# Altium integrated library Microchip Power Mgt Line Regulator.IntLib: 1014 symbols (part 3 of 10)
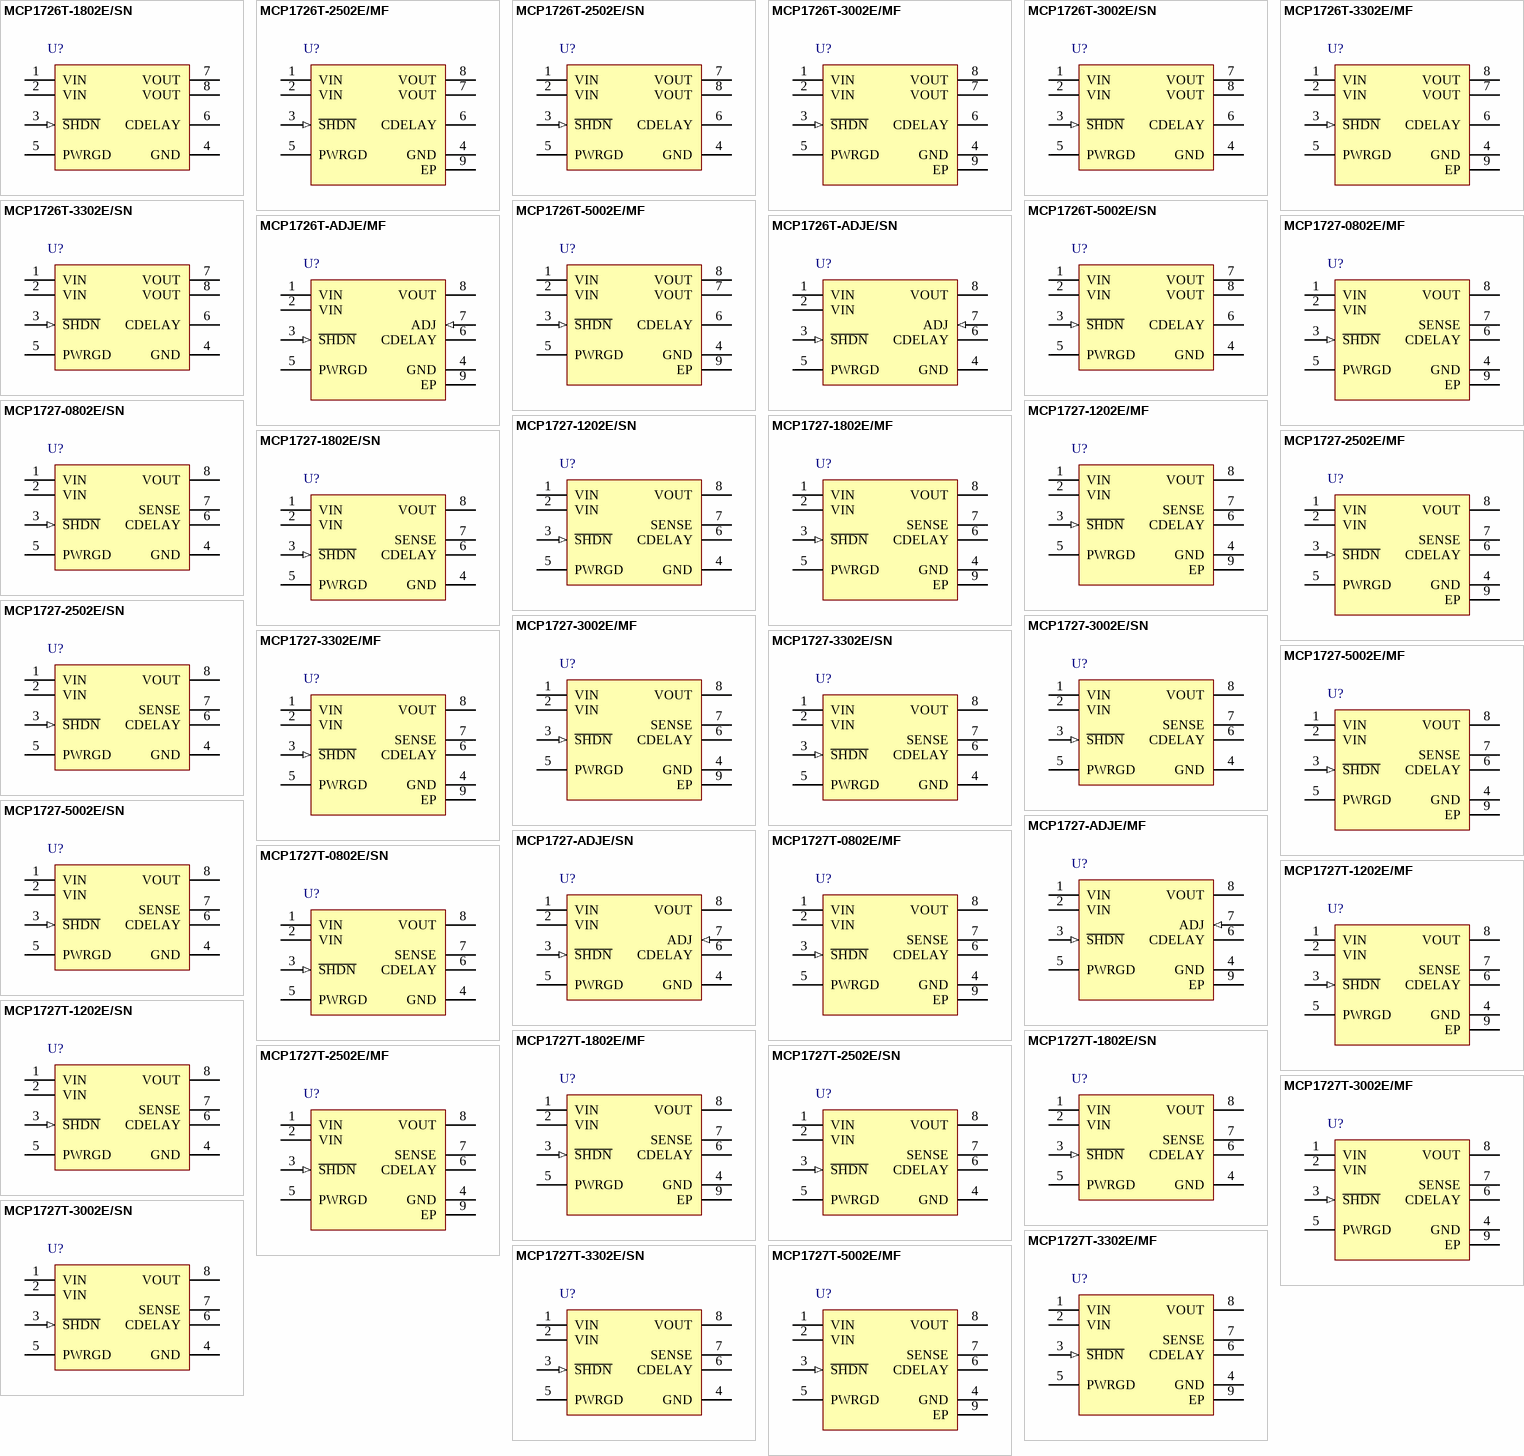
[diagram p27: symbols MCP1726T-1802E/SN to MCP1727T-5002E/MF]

## MCP1727-5002E/SN
designator U?
1.5A, Low Voltage, Low Quiescent Current LDO Regulator, 8-Pin SOIC 150mil, Extended Temperature
footprint SOIC-SN8_N (SOIC, 8-Leads, Body 4.9x3.8mm, Pitch 1.27mm, IPC Medium Density)
footprint SOIC-SN8_L (SOIC, 8-Leads, Body 4.9x3.8mm, Pitch 1.27mm, IPC High Density)
footprint SOIC-SN8_M (SOIC, 8-Leads, Body 4.9x3.8mm, Pitch 1.27mm, IPC Low Density)
pins: 1 VIN (power), 2 VIN (power), 3 ~{SHDN} (in), 4 GND (power), 5 PWRGD (power), 6 CDELAY, 7 SENSE, 8 VOUT (power)

## MCP1727-ADJE/MF
designator U?
1.5A, Low Voltage, Low Quiescent Current LDO Regulator, 8-Pin DFN, Extended Temperature
footprint DFN-MF8 (SON, 8-Leads, Body 3x3mm, Pitch 0.65mm, Microchip Recommended)
pins: 1 VIN (power), 2 VIN (power), 3 ~{SHDN} (in), 4 GND (power), 5 PWRGD (power), 6 CDELAY, 7 ADJ (in), 8 VOUT (power), 9 EP (power)

## MCP1727-ADJE/SN
designator U?
1.5A, Low Voltage, Low Quiescent Current LDO Regulator, 8-Pin SOIC 150mil, Extended Temperature
footprint SOIC-SN8_N (SOIC, 8-Leads, Body 4.9x3.8mm, Pitch 1.27mm, IPC Medium Density)
footprint SOIC-SN8_L (SOIC, 8-Leads, Body 4.9x3.8mm, Pitch 1.27mm, IPC High Density)
footprint SOIC-SN8_M (SOIC, 8-Leads, Body 4.9x3.8mm, Pitch 1.27mm, IPC Low Density)
pins: 1 VIN (power), 2 VIN (power), 3 ~{SHDN} (in), 4 GND (power), 5 PWRGD (power), 6 CDELAY, 7 ADJ (in), 8 VOUT (power)

## MCP1727T-0802E/MF
designator U?
1.5A, Low Voltage, Low Quiescent Current LDO Regulator, 8-Pin DFN, Extended Temperature, Tape and Reel
footprint DFN-MF8 (SON, 8-Leads, Body 3x3mm, Pitch 0.65mm, Microchip Recommended)
pins: 1 VIN (power), 2 VIN (power), 3 ~{SHDN} (in), 4 GND (power), 5 PWRGD (power), 6 CDELAY, 7 SENSE, 8 VOUT (power), 9 EP (power)

## MCP1727T-0802E/SN
designator U?
1.5A, Low Voltage, Low Quiescent Current LDO Regulator, 8-Pin SOIC 150mil, Extended Temperature, Tape and Reel
footprint SOIC-SN8_N (SOIC, 8-Leads, Body 4.9x3.8mm, Pitch 1.27mm, IPC Medium Density)
footprint SOIC-SN8_L (SOIC, 8-Leads, Body 4.9x3.8mm, Pitch 1.27mm, IPC High Density)
footprint SOIC-SN8_M (SOIC, 8-Leads, Body 4.9x3.8mm, Pitch 1.27mm, IPC Low Density)
pins: 1 VIN (power), 2 VIN (power), 3 ~{SHDN} (in), 4 GND (power), 5 PWRGD (power), 6 CDELAY, 7 SENSE, 8 VOUT (power)

## MCP1727T-1202E/MF
designator U?
1.5A, Low Voltage, Low Quiescent Current LDO Regulator, 8-Pin DFN, Extended Temperature, Tape and Reel
footprint DFN-MF8 (SON, 8-Leads, Body 3x3mm, Pitch 0.65mm, Microchip Recommended)
pins: 1 VIN (power), 2 VIN (power), 3 ~{SHDN} (in), 4 GND (power), 5 PWRGD (power), 6 CDELAY, 7 SENSE, 8 VOUT (power), 9 EP (power)

## MCP1727T-1202E/SN
designator U?
1.5A, Low Voltage, Low Quiescent Current LDO Regulator, 8-Pin SOIC 150mil, Extended Temperature, Tape and Reel
footprint SOIC-SN8_N (SOIC, 8-Leads, Body 4.9x3.8mm, Pitch 1.27mm, IPC Medium Density)
footprint SOIC-SN8_L (SOIC, 8-Leads, Body 4.9x3.8mm, Pitch 1.27mm, IPC High Density)
footprint SOIC-SN8_M (SOIC, 8-Leads, Body 4.9x3.8mm, Pitch 1.27mm, IPC Low Density)
pins: 1 VIN (power), 2 VIN (power), 3 ~{SHDN} (in), 4 GND (power), 5 PWRGD (power), 6 CDELAY, 7 SENSE, 8 VOUT (power)

## MCP1727T-1802E/MF
designator U?
1.5A, Low Voltage, Low Quiescent Current LDO Regulator, 8-Pin DFN, Extended Temperature, Tape and Reel
footprint DFN-MF8 (SON, 8-Leads, Body 3x3mm, Pitch 0.65mm, Microchip Recommended)
pins: 1 VIN (power), 2 VIN (power), 3 ~{SHDN} (in), 4 GND (power), 5 PWRGD (power), 6 CDELAY, 7 SENSE, 8 VOUT (power), 9 EP (power)

## MCP1727T-1802E/SN
designator U?
1.5A, Low Voltage, Low Quiescent Current LDO Regulator, 8-Pin SOIC 150mil, Extended Temperature, Tape and Reel
footprint SOIC-SN8_N (SOIC, 8-Leads, Body 4.9x3.8mm, Pitch 1.27mm, IPC Medium Density)
footprint SOIC-SN8_L (SOIC, 8-Leads, Body 4.9x3.8mm, Pitch 1.27mm, IPC High Density)
footprint SOIC-SN8_M (SOIC, 8-Leads, Body 4.9x3.8mm, Pitch 1.27mm, IPC Low Density)
pins: 1 VIN (power), 2 VIN (power), 3 ~{SHDN} (in), 4 GND (power), 5 PWRGD (power), 6 CDELAY, 7 SENSE, 8 VOUT (power)

## MCP1727T-2502E/MF
designator U?
1.5A, Low Voltage, Low Quiescent Current LDO Regulator, 8-Pin DFN, Extended Temperature, Tape and Reel
footprint DFN-MF8 (SON, 8-Leads, Body 3x3mm, Pitch 0.65mm, Microchip Recommended)
pins: 1 VIN (power), 2 VIN (power), 3 ~{SHDN} (in), 4 GND (power), 5 PWRGD (power), 6 CDELAY, 7 SENSE, 8 VOUT (power), 9 EP (power)

## MCP1727T-2502E/SN
designator U?
1.5A, Low Voltage, Low Quiescent Current LDO Regulator, 8-Pin SOIC 150mil, Extended Temperature, Tape and Reel
footprint SOIC-SN8_N (SOIC, 8-Leads, Body 4.9x3.8mm, Pitch 1.27mm, IPC Medium Density)
footprint SOIC-SN8_L (SOIC, 8-Leads, Body 4.9x3.8mm, Pitch 1.27mm, IPC High Density)
footprint SOIC-SN8_M (SOIC, 8-Leads, Body 4.9x3.8mm, Pitch 1.27mm, IPC Low Density)
pins: 1 VIN (power), 2 VIN (power), 3 ~{SHDN} (in), 4 GND (power), 5 PWRGD (power), 6 CDELAY, 7 SENSE, 8 VOUT (power)

## MCP1727T-3002E/MF
designator U?
1.5A, Low Voltage, Low Quiescent Current LDO Regulator, 8-Pin DFN, Extended Temperature, Tape and Reel
footprint DFN-MF8 (SON, 8-Leads, Body 3x3mm, Pitch 0.65mm, Microchip Recommended)
pins: 1 VIN (power), 2 VIN (power), 3 ~{SHDN} (in), 4 GND (power), 5 PWRGD (power), 6 CDELAY, 7 SENSE, 8 VOUT (power), 9 EP (power)

## MCP1727T-3002E/SN
designator U?
1.5A, Low Voltage, Low Quiescent Current LDO Regulator, 8-Pin SOIC 150mil, Extended Temperature, Tape and Reel
footprint SOIC-SN8_N (SOIC, 8-Leads, Body 4.9x3.8mm, Pitch 1.27mm, IPC Medium Density)
footprint SOIC-SN8_L (SOIC, 8-Leads, Body 4.9x3.8mm, Pitch 1.27mm, IPC High Density)
footprint SOIC-SN8_M (SOIC, 8-Leads, Body 4.9x3.8mm, Pitch 1.27mm, IPC Low Density)
pins: 1 VIN (power), 2 VIN (power), 3 ~{SHDN} (in), 4 GND (power), 5 PWRGD (power), 6 CDELAY, 7 SENSE, 8 VOUT (power)

## MCP1727T-3302E/MF
designator U?
1.5A, Low Voltage, Low Quiescent Current LDO Regulator, 8-Pin DFN, Extended Temperature, Tape and Reel
footprint DFN-MF8 (SON, 8-Leads, Body 3x3mm, Pitch 0.65mm, Microchip Recommended)
pins: 1 VIN (power), 2 VIN (power), 3 ~{SHDN} (in), 4 GND (power), 5 PWRGD (power), 6 CDELAY, 7 SENSE, 8 VOUT (power), 9 EP (power)

## MCP1727T-3302E/SN
designator U?
1.5A, Low Voltage, Low Quiescent Current LDO Regulator, 8-Pin SOIC 150mil, Extended Temperature, Tape and Reel
footprint SOIC-SN8_N (SOIC, 8-Leads, Body 4.9x3.8mm, Pitch 1.27mm, IPC Medium Density)
footprint SOIC-SN8_L (SOIC, 8-Leads, Body 4.9x3.8mm, Pitch 1.27mm, IPC High Density)
footprint SOIC-SN8_M (SOIC, 8-Leads, Body 4.9x3.8mm, Pitch 1.27mm, IPC Low Density)
pins: 1 VIN (power), 2 VIN (power), 3 ~{SHDN} (in), 4 GND (power), 5 PWRGD (power), 6 CDELAY, 7 SENSE, 8 VOUT (power)

## MCP1727T-5002E/MF
designator U?
1.5A, Low Voltage, Low Quiescent Current LDO Regulator, 8-Pin DFN, Extended Temperature, Tape and Reel
footprint DFN-MF8 (SON, 8-Leads, Body 3x3mm, Pitch 0.65mm, Microchip Recommended)
pins: 1 VIN (power), 2 VIN (power), 3 ~{SHDN} (in), 4 GND (power), 5 PWRGD (power), 6 CDELAY, 7 SENSE, 8 VOUT (power), 9 EP (power)

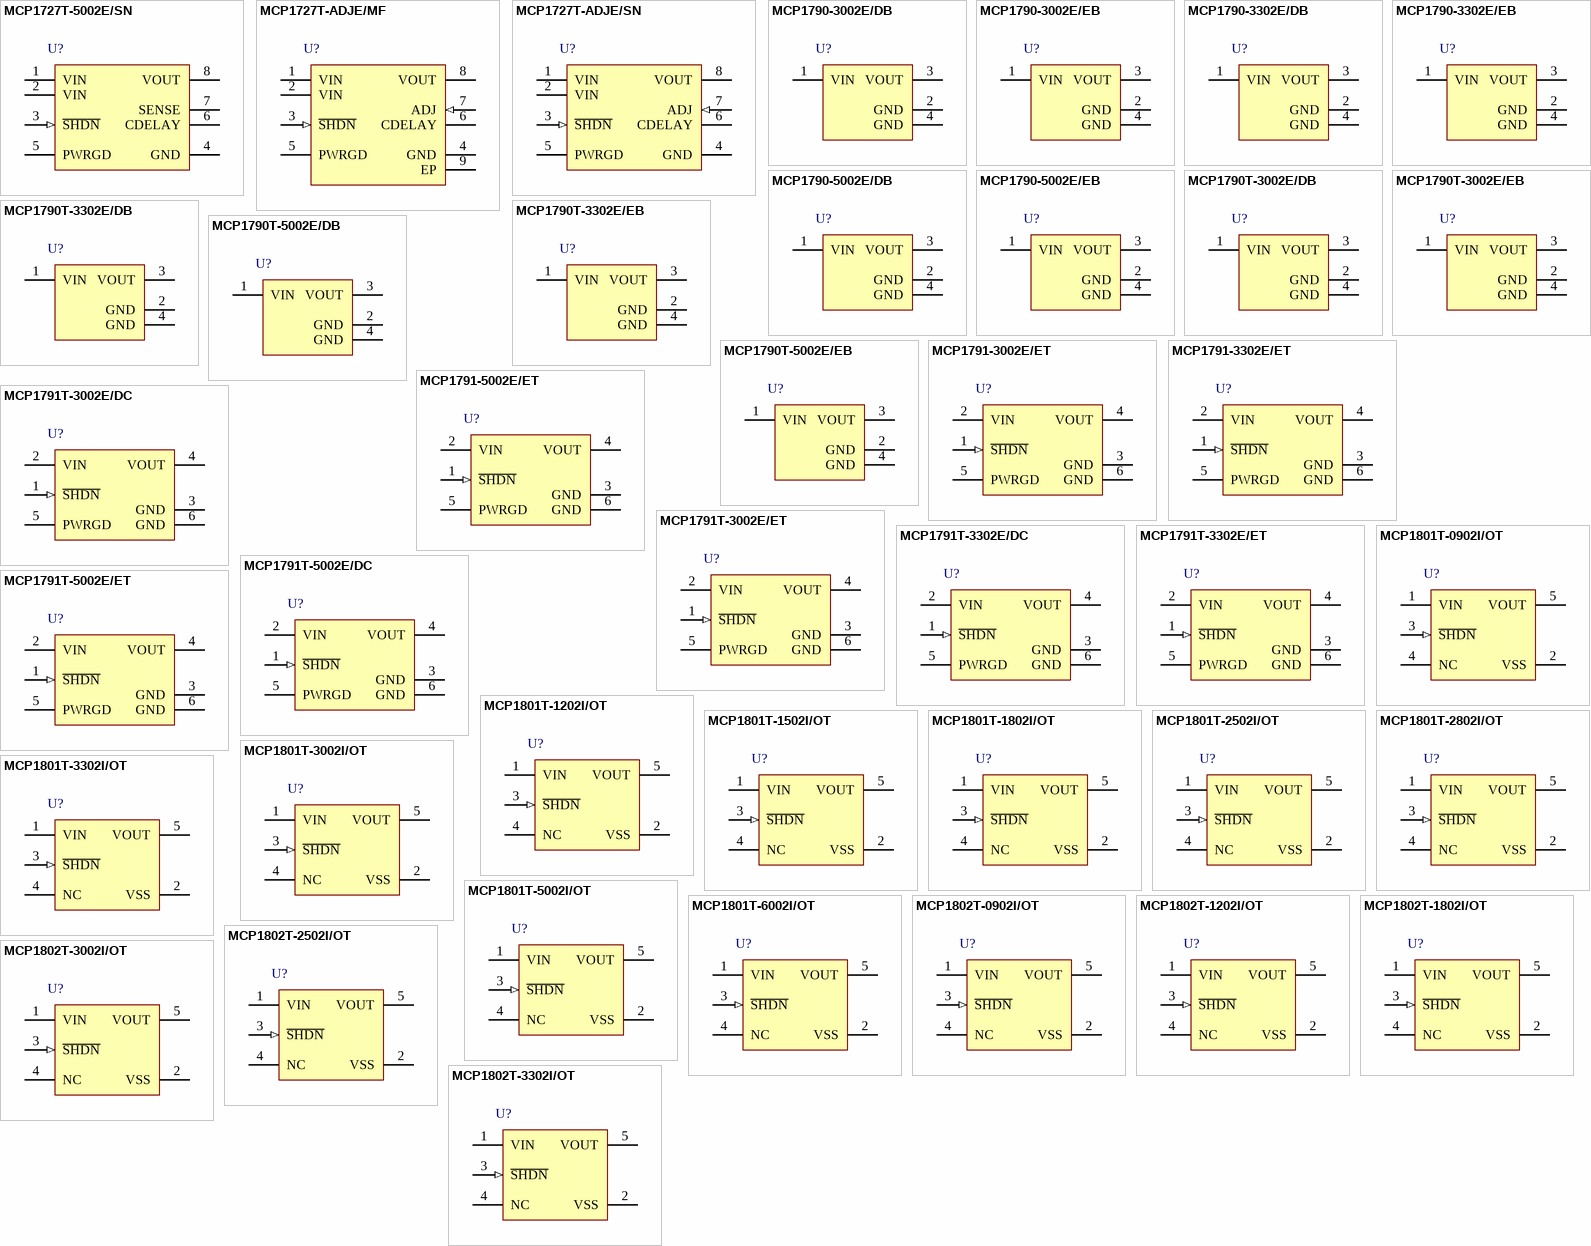
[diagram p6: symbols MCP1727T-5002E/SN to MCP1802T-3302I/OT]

## MCP1727T-5002E/SN
designator U?
1.5A, Low Voltage, Low Quiescent Current LDO Regulator, 8-Pin SOIC 150mil, Extended Temperature, Tape and Reel
footprint SOIC-SN8_N (SOIC, 8-Leads, Body 4.9x3.8mm, Pitch 1.27mm, IPC Medium Density)
footprint SOIC-SN8_L (SOIC, 8-Leads, Body 4.9x3.8mm, Pitch 1.27mm, IPC High Density)
footprint SOIC-SN8_M (SOIC, 8-Leads, Body 4.9x3.8mm, Pitch 1.27mm, IPC Low Density)
pins: 1 VIN (power), 2 VIN (power), 3 ~{SHDN} (in), 4 GND (power), 5 PWRGD (power), 6 CDELAY, 7 SENSE, 8 VOUT (power)

## MCP1727T-ADJE/MF
designator U?
1.5A, Low Voltage, Low Quiescent Current LDO Regulator, 8-Pin DFN, Extended Temperature, Tape and Reel
footprint DFN-MF8 (SON, 8-Leads, Body 3x3mm, Pitch 0.65mm, Microchip Recommended)
pins: 1 VIN (power), 2 VIN (power), 3 ~{SHDN} (in), 4 GND (power), 5 PWRGD (power), 6 CDELAY, 7 ADJ (in), 8 VOUT (power), 9 EP (power)

## MCP1727T-ADJE/SN
designator U?
1.5A, Low Voltage, Low Quiescent Current LDO Regulator, 8-Pin SOIC 150mil, Extended Temperature, Tape and Reel
footprint SOIC-SN8_N (SOIC, 8-Leads, Body 4.9x3.8mm, Pitch 1.27mm, IPC Medium Density)
footprint SOIC-SN8_L (SOIC, 8-Leads, Body 4.9x3.8mm, Pitch 1.27mm, IPC High Density)
footprint SOIC-SN8_M (SOIC, 8-Leads, Body 4.9x3.8mm, Pitch 1.27mm, IPC Low Density)
pins: 1 VIN (power), 2 VIN (power), 3 ~{SHDN} (in), 4 GND (power), 5 PWRGD (power), 6 CDELAY, 7 ADJ (in), 8 VOUT (power)

## MCP1790-3002E/DB
designator U?
70 mA, High Voltage Regulator, 3-Pin SOT-223, Extended Temperature
footprint SOT-223-DB3_N (SOT223, 4-Leads, Body 6.5x3.5mm, Pitch 2.3mm, Lead Span 7mm, IPC Medium Density)
footprint SOT-223-DB3_L (SOT223, 4-Leads, Body 6.5x3.5mm, Pitch 2.3mm, Lead Span 7mm, IPC High Density)
footprint SOT-223-DB3_M (SOT223, 4-Leads, Body 6.5x3.5mm, Pitch 2.3mm, Lead Span 7mm, IPC Low Density)
pins: 1 VIN (power), 2 GND (power), 3 VOUT (power), 4 GND (power)

## MCP1790-3002E/EB
designator U?
70 mA, High Voltage Regulator, 3-Pin DDPAK, Extended Temperature
footprint DDPAK-EB3_N (D2-PAK, 4-Leads, Body 9x10.2mm, Pitch 2.54mm, Lead Span 14.9mm, IPC Medium Density)
footprint DDPAK-EB3_L (D2-PAK, 4-Leads, Body 9x10.2mm, Pitch 2.54mm, Lead Span 14.9mm, IPC High Density)
footprint DDPAK-EB3_M (D2-PAK, 4-Leads, Body 9x10.2mm, Pitch 2.54mm, Lead Span 14.9mm, IPC Low Density)
pins: 1 VIN (power), 2 GND (power), 3 VOUT (power), 4 GND (power)

## MCP1790-3302E/DB
designator U?
70 mA, High Voltage Regulator, 3-Pin SOT-223, Extended Temperature
footprint SOT-223-DB3_N (SOT223, 4-Leads, Body 6.5x3.5mm, Pitch 2.3mm, Lead Span 7mm, IPC Medium Density)
footprint SOT-223-DB3_L (SOT223, 4-Leads, Body 6.5x3.5mm, Pitch 2.3mm, Lead Span 7mm, IPC High Density)
footprint SOT-223-DB3_M (SOT223, 4-Leads, Body 6.5x3.5mm, Pitch 2.3mm, Lead Span 7mm, IPC Low Density)
pins: 1 VIN (power), 2 GND (power), 3 VOUT (power), 4 GND (power)

## MCP1790-3302E/EB
designator U?
70 mA, High Voltage Regulator, 3-Pin DDPAK, Extended Temperature
footprint DDPAK-EB3_N (D2-PAK, 4-Leads, Body 9x10.2mm, Pitch 2.54mm, Lead Span 14.9mm, IPC Medium Density)
footprint DDPAK-EB3_L (D2-PAK, 4-Leads, Body 9x10.2mm, Pitch 2.54mm, Lead Span 14.9mm, IPC High Density)
footprint DDPAK-EB3_M (D2-PAK, 4-Leads, Body 9x10.2mm, Pitch 2.54mm, Lead Span 14.9mm, IPC Low Density)
pins: 1 VIN (power), 2 GND (power), 3 VOUT (power), 4 GND (power)

## MCP1790-5002E/DB
designator U?
70 mA, High Voltage Regulator, 3-Pin SOT-223, Extended Temperature
footprint SOT-223-DB3_N (SOT223, 4-Leads, Body 6.5x3.5mm, Pitch 2.3mm, Lead Span 7mm, IPC Medium Density)
footprint SOT-223-DB3_L (SOT223, 4-Leads, Body 6.5x3.5mm, Pitch 2.3mm, Lead Span 7mm, IPC High Density)
footprint SOT-223-DB3_M (SOT223, 4-Leads, Body 6.5x3.5mm, Pitch 2.3mm, Lead Span 7mm, IPC Low Density)
pins: 1 VIN (power), 2 GND (power), 3 VOUT (power), 4 GND (power)

## MCP1790-5002E/EB
designator U?
70 mA, High Voltage Regulator, 3-Pin DDPAK, Extended Temperature
footprint DDPAK-EB3_N (D2-PAK, 4-Leads, Body 9x10.2mm, Pitch 2.54mm, Lead Span 14.9mm, IPC Medium Density)
footprint DDPAK-EB3_L (D2-PAK, 4-Leads, Body 9x10.2mm, Pitch 2.54mm, Lead Span 14.9mm, IPC High Density)
footprint DDPAK-EB3_M (D2-PAK, 4-Leads, Body 9x10.2mm, Pitch 2.54mm, Lead Span 14.9mm, IPC Low Density)
pins: 1 VIN (power), 2 GND (power), 3 VOUT (power), 4 GND (power)

## MCP1790T-3002E/DB
designator U?
70 mA, High Voltage Regulator, 3-Pin SOT-223, Extended Temperature, Tape and Reel
footprint SOT-223-DB3_N (SOT223, 4-Leads, Body 6.5x3.5mm, Pitch 2.3mm, Lead Span 7mm, IPC Medium Density)
footprint SOT-223-DB3_L (SOT223, 4-Leads, Body 6.5x3.5mm, Pitch 2.3mm, Lead Span 7mm, IPC High Density)
footprint SOT-223-DB3_M (SOT223, 4-Leads, Body 6.5x3.5mm, Pitch 2.3mm, Lead Span 7mm, IPC Low Density)
pins: 1 VIN (power), 2 GND (power), 3 VOUT (power), 4 GND (power)

## MCP1790T-3002E/EB
designator U?
70 mA, High Voltage Regulator, 3-Pin DDPAK, Extended Temperature, Tape and Reel
footprint DDPAK-EB3_N (D2-PAK, 4-Leads, Body 9x10.2mm, Pitch 2.54mm, Lead Span 14.9mm, IPC Medium Density)
footprint DDPAK-EB3_L (D2-PAK, 4-Leads, Body 9x10.2mm, Pitch 2.54mm, Lead Span 14.9mm, IPC High Density)
footprint DDPAK-EB3_M (D2-PAK, 4-Leads, Body 9x10.2mm, Pitch 2.54mm, Lead Span 14.9mm, IPC Low Density)
pins: 1 VIN (power), 2 GND (power), 3 VOUT (power), 4 GND (power)

## MCP1790T-3302E/DB
designator U?
70 mA, High Voltage Regulator, 3-Pin SOT-223, Extended Temperature, Tape and Reel
footprint SOT-223-DB3_N (SOT223, 4-Leads, Body 6.5x3.5mm, Pitch 2.3mm, Lead Span 7mm, IPC Medium Density)
footprint SOT-223-DB3_L (SOT223, 4-Leads, Body 6.5x3.5mm, Pitch 2.3mm, Lead Span 7mm, IPC High Density)
footprint SOT-223-DB3_M (SOT223, 4-Leads, Body 6.5x3.5mm, Pitch 2.3mm, Lead Span 7mm, IPC Low Density)
pins: 1 VIN (power), 2 GND (power), 3 VOUT (power), 4 GND (power)

## MCP1790T-3302E/EB
designator U?
70 mA, High Voltage Regulator, 3-Pin DDPAK, Extended Temperature, Tape and Reel
footprint DDPAK-EB3_N (D2-PAK, 4-Leads, Body 9x10.2mm, Pitch 2.54mm, Lead Span 14.9mm, IPC Medium Density)
footprint DDPAK-EB3_L (D2-PAK, 4-Leads, Body 9x10.2mm, Pitch 2.54mm, Lead Span 14.9mm, IPC High Density)
footprint DDPAK-EB3_M (D2-PAK, 4-Leads, Body 9x10.2mm, Pitch 2.54mm, Lead Span 14.9mm, IPC Low Density)
pins: 1 VIN (power), 2 GND (power), 3 VOUT (power), 4 GND (power)

## MCP1790T-5002E/DB
designator U?
70 mA, High Voltage Regulator, 3-Pin SOT-223, Extended Temperature, Tape and Reel
footprint SOT-223-DB3_N (SOT223, 4-Leads, Body 6.5x3.5mm, Pitch 2.3mm, Lead Span 7mm, IPC Medium Density)
footprint SOT-223-DB3_L (SOT223, 4-Leads, Body 6.5x3.5mm, Pitch 2.3mm, Lead Span 7mm, IPC High Density)
footprint SOT-223-DB3_M (SOT223, 4-Leads, Body 6.5x3.5mm, Pitch 2.3mm, Lead Span 7mm, IPC Low Density)
pins: 1 VIN (power), 2 GND (power), 3 VOUT (power), 4 GND (power)

## MCP1790T-5002E/EB
designator U?
70 mA, High Voltage Regulator, 3-Pin DDPAK, Extended Temperature, Tape and Reel
footprint DDPAK-EB3_N (D2-PAK, 4-Leads, Body 9x10.2mm, Pitch 2.54mm, Lead Span 14.9mm, IPC Medium Density)
footprint DDPAK-EB3_L (D2-PAK, 4-Leads, Body 9x10.2mm, Pitch 2.54mm, Lead Span 14.9mm, IPC High Density)
footprint DDPAK-EB3_M (D2-PAK, 4-Leads, Body 9x10.2mm, Pitch 2.54mm, Lead Span 14.9mm, IPC Low Density)
pins: 1 VIN (power), 2 GND (power), 3 VOUT (power), 4 GND (power)

## MCP1791-3002E/ET
designator U?
70 mA, High Voltage Regulator, 5-Pin DDPAK, Extended Temperature
footprint DDPAK-ET5_N (D2-PAK, 6-Leads, Body 9x10.2mm, Pitch 1.7mm, Lead Span 14.9mm, IPC Medium Density)
footprint DDPAK-ET5_L (D2-PAK, 6-Leads, Body 9x10.2mm, Pitch 1.7mm, Lead Span 14.9mm, IPC High Density)
footprint DDPAK-ET5_M (D2-PAK, 6-Leads, Body 9x10.2mm, Pitch 1.7mm, Lead Span 14.9mm, IPC Low Density)
pins: 1 ~{SHDN} (in), 2 VIN (power), 3 GND (power), 4 VOUT (power), 5 PWRGD (power), 6 GND (power)

## MCP1791-3302E/ET
designator U?
70 mA, High Voltage Regulator, 5-Pin DDPAK, Extended Temperature
footprint DDPAK-ET5_N (D2-PAK, 6-Leads, Body 9x10.2mm, Pitch 1.7mm, Lead Span 14.9mm, IPC Medium Density)
footprint DDPAK-ET5_L (D2-PAK, 6-Leads, Body 9x10.2mm, Pitch 1.7mm, Lead Span 14.9mm, IPC High Density)
footprint DDPAK-ET5_M (D2-PAK, 6-Leads, Body 9x10.2mm, Pitch 1.7mm, Lead Span 14.9mm, IPC Low Density)
pins: 1 ~{SHDN} (in), 2 VIN (power), 3 GND (power), 4 VOUT (power), 5 PWRGD (power), 6 GND (power)

## MCP1791-5002E/ET
designator U?
70 mA, High Voltage Regulator, 5-Pin DDPAK, Extended Temperature
footprint DDPAK-ET5_N (D2-PAK, 6-Leads, Body 9x10.2mm, Pitch 1.7mm, Lead Span 14.9mm, IPC Medium Density)
footprint DDPAK-ET5_L (D2-PAK, 6-Leads, Body 9x10.2mm, Pitch 1.7mm, Lead Span 14.9mm, IPC High Density)
footprint DDPAK-ET5_M (D2-PAK, 6-Leads, Body 9x10.2mm, Pitch 1.7mm, Lead Span 14.9mm, IPC Low Density)
pins: 1 ~{SHDN} (in), 2 VIN (power), 3 GND (power), 4 VOUT (power), 5 PWRGD (power), 6 GND (power)

## MCP1791T-3002E/DC
designator U?
70 mA, High Voltage Regulator, 5-Pin SOT-223, Extended Temperature, Tape and Reel
footprint SOT-223-DC5_N (SOT223, 6-Leads, Body 6.5x3.5mm, Pitch 1.27mm, Lead Span 7mm, IPC Medium Density)
footprint SOT-223-DC5_L (SOT223, 6-Leads, Body 6.5x3.5mm, Pitch 1.27mm, Lead Span 7mm, IPC High Density)
footprint SOT-223-DC5_M (SOT223, 6-Leads, Body 6.5x3.5mm, Pitch 1.27mm, Lead Span 7mm, IPC Low Density)
pins: 1 ~{SHDN} (in), 2 VIN (power), 3 GND (power), 4 VOUT (power), 5 PWRGD (power), 6 GND (power)

## MCP1791T-3002E/ET
designator U?
70 mA, High Voltage Regulator, 5-Pin DDPAK, Extended Temperature, Tape and Reel
footprint DDPAK-ET5_N (D2-PAK, 6-Leads, Body 9x10.2mm, Pitch 1.7mm, Lead Span 14.9mm, IPC Medium Density)
footprint DDPAK-ET5_L (D2-PAK, 6-Leads, Body 9x10.2mm, Pitch 1.7mm, Lead Span 14.9mm, IPC High Density)
footprint DDPAK-ET5_M (D2-PAK, 6-Leads, Body 9x10.2mm, Pitch 1.7mm, Lead Span 14.9mm, IPC Low Density)
pins: 1 ~{SHDN} (in), 2 VIN (power), 3 GND (power), 4 VOUT (power), 5 PWRGD (power), 6 GND (power)

## MCP1791T-3302E/DC
designator U?
70 mA, High Voltage Regulator, 5-Pin SOT-223, Extended Temperature, Tape and Reel
footprint SOT-223-DC5_N (SOT223, 6-Leads, Body 6.5x3.5mm, Pitch 1.27mm, Lead Span 7mm, IPC Medium Density)
footprint SOT-223-DC5_L (SOT223, 6-Leads, Body 6.5x3.5mm, Pitch 1.27mm, Lead Span 7mm, IPC High Density)
footprint SOT-223-DC5_M (SOT223, 6-Leads, Body 6.5x3.5mm, Pitch 1.27mm, Lead Span 7mm, IPC Low Density)
pins: 1 ~{SHDN} (in), 2 VIN (power), 3 GND (power), 4 VOUT (power), 5 PWRGD (power), 6 GND (power)

## MCP1791T-3302E/ET
designator U?
70 mA, High Voltage Regulator, 5-Pin DDPAK, Extended Temperature, Tape and Reel
footprint DDPAK-ET5_N (D2-PAK, 6-Leads, Body 9x10.2mm, Pitch 1.7mm, Lead Span 14.9mm, IPC Medium Density)
footprint DDPAK-ET5_L (D2-PAK, 6-Leads, Body 9x10.2mm, Pitch 1.7mm, Lead Span 14.9mm, IPC High Density)
footprint DDPAK-ET5_M (D2-PAK, 6-Leads, Body 9x10.2mm, Pitch 1.7mm, Lead Span 14.9mm, IPC Low Density)
pins: 1 ~{SHDN} (in), 2 VIN (power), 3 GND (power), 4 VOUT (power), 5 PWRGD (power), 6 GND (power)

## MCP1791T-5002E/DC
designator U?
70 mA, High Voltage Regulator, 5-Pin SOT-223, Extended Temperature, Tape and Reel
footprint SOT-223-DC5_N (SOT223, 6-Leads, Body 6.5x3.5mm, Pitch 1.27mm, Lead Span 7mm, IPC Medium Density)
footprint SOT-223-DC5_L (SOT223, 6-Leads, Body 6.5x3.5mm, Pitch 1.27mm, Lead Span 7mm, IPC High Density)
footprint SOT-223-DC5_M (SOT223, 6-Leads, Body 6.5x3.5mm, Pitch 1.27mm, Lead Span 7mm, IPC Low Density)
pins: 1 ~{SHDN} (in), 2 VIN (power), 3 GND (power), 4 VOUT (power), 5 PWRGD (power), 6 GND (power)

## MCP1791T-5002E/ET
designator U?
70 mA, High Voltage Regulator, 5-Pin DDPAK, Extended Temperature, Tape and Reel
footprint DDPAK-ET5_N (D2-PAK, 6-Leads, Body 9x10.2mm, Pitch 1.7mm, Lead Span 14.9mm, IPC Medium Density)
footprint DDPAK-ET5_L (D2-PAK, 6-Leads, Body 9x10.2mm, Pitch 1.7mm, Lead Span 14.9mm, IPC High Density)
footprint DDPAK-ET5_M (D2-PAK, 6-Leads, Body 9x10.2mm, Pitch 1.7mm, Lead Span 14.9mm, IPC Low Density)
pins: 1 ~{SHDN} (in), 2 VIN (power), 3 GND (power), 4 VOUT (power), 5 PWRGD (power), 6 GND (power)

## MCP1801T-0902I/OT
designator U?
150 mA, High PSRR, Low Quiescent Current LDO, 5-Pin SOT-23, Industrial Temperature, Tape and Reel
footprint SOT-23-OT5_N (SOT23, 5-Leads, Body 2.9x1.6mm, Pitch 0.95mm, Lead Span 2.7mm, IPC Medium Density)
footprint SOT-23-OT5_L (SOT23, 5-Leads, Body 2.9x1.6mm, Pitch 0.95mm, Lead Span 2.7mm, IPC High Density)
footprint SOT-23-OT5_M (SOT23, 5-Leads, Body 2.9x1.6mm, Pitch 0.95mm, Lead Span 2.7mm, IPC Low Density)
pins: 1 VIN (power), 2 VSS (power), 3 ~{SHDN} (in), 4 NC, 5 VOUT (power)

## MCP1801T-1202I/OT
designator U?
150 mA, High PSRR, Low Quiescent Current LDO, 5-Pin SOT-23, Industrial Temperature, Tape and Reel
footprint SOT-23-OT5_N (SOT23, 5-Leads, Body 2.9x1.6mm, Pitch 0.95mm, Lead Span 2.7mm, IPC Medium Density)
footprint SOT-23-OT5_L (SOT23, 5-Leads, Body 2.9x1.6mm, Pitch 0.95mm, Lead Span 2.7mm, IPC High Density)
footprint SOT-23-OT5_M (SOT23, 5-Leads, Body 2.9x1.6mm, Pitch 0.95mm, Lead Span 2.7mm, IPC Low Density)
pins: 1 VIN (power), 2 VSS (power), 3 ~{SHDN} (in), 4 NC, 5 VOUT (power)

## MCP1801T-1502I/OT
designator U?
150 mA, High PSRR, Low Quiescent Current LDO, 5-Pin SOT-23, Industrial Temperature, Tape and Reel
footprint SOT-23-OT5_N (SOT23, 5-Leads, Body 2.9x1.6mm, Pitch 0.95mm, Lead Span 2.7mm, IPC Medium Density)
footprint SOT-23-OT5_L (SOT23, 5-Leads, Body 2.9x1.6mm, Pitch 0.95mm, Lead Span 2.7mm, IPC High Density)
footprint SOT-23-OT5_M (SOT23, 5-Leads, Body 2.9x1.6mm, Pitch 0.95mm, Lead Span 2.7mm, IPC Low Density)
pins: 1 VIN (power), 2 VSS (power), 3 ~{SHDN} (in), 4 NC, 5 VOUT (power)

## MCP1801T-1802I/OT
designator U?
150 mA, High PSRR, Low Quiescent Current LDO, 5-Pin SOT-23, Industrial Temperature, Tape and Reel
footprint SOT-23-OT5_N (SOT23, 5-Leads, Body 2.9x1.6mm, Pitch 0.95mm, Lead Span 2.7mm, IPC Medium Density)
footprint SOT-23-OT5_L (SOT23, 5-Leads, Body 2.9x1.6mm, Pitch 0.95mm, Lead Span 2.7mm, IPC High Density)
footprint SOT-23-OT5_M (SOT23, 5-Leads, Body 2.9x1.6mm, Pitch 0.95mm, Lead Span 2.7mm, IPC Low Density)
pins: 1 VIN (power), 2 VSS (power), 3 ~{SHDN} (in), 4 NC, 5 VOUT (power)

## MCP1801T-2502I/OT
designator U?
150 mA, High PSRR, Low Quiescent Current LDO, 5-Pin SOT-23, Industrial Temperature, Tape and Reel
footprint SOT-23-OT5_N (SOT23, 5-Leads, Body 2.9x1.6mm, Pitch 0.95mm, Lead Span 2.7mm, IPC Medium Density)
footprint SOT-23-OT5_L (SOT23, 5-Leads, Body 2.9x1.6mm, Pitch 0.95mm, Lead Span 2.7mm, IPC High Density)
footprint SOT-23-OT5_M (SOT23, 5-Leads, Body 2.9x1.6mm, Pitch 0.95mm, Lead Span 2.7mm, IPC Low Density)
pins: 1 VIN (power), 2 VSS (power), 3 ~{SHDN} (in), 4 NC, 5 VOUT (power)

## MCP1801T-2802I/OT
designator U?
150 mA, High PSRR, Low Quiescent Current LDO, 5-Pin SOT-23, Industrial Temperature, Tape and Reel
footprint SOT-23-OT5_N (SOT23, 5-Leads, Body 2.9x1.6mm, Pitch 0.95mm, Lead Span 2.7mm, IPC Medium Density)
footprint SOT-23-OT5_L (SOT23, 5-Leads, Body 2.9x1.6mm, Pitch 0.95mm, Lead Span 2.7mm, IPC High Density)
footprint SOT-23-OT5_M (SOT23, 5-Leads, Body 2.9x1.6mm, Pitch 0.95mm, Lead Span 2.7mm, IPC Low Density)
pins: 1 VIN (power), 2 VSS (power), 3 ~{SHDN} (in), 4 NC, 5 VOUT (power)

## MCP1801T-3002I/OT
designator U?
150 mA, High PSRR, Low Quiescent Current LDO, 5-Pin SOT-23, Industrial Temperature, Tape and Reel
footprint SOT-23-OT5_N (SOT23, 5-Leads, Body 2.9x1.6mm, Pitch 0.95mm, Lead Span 2.7mm, IPC Medium Density)
footprint SOT-23-OT5_L (SOT23, 5-Leads, Body 2.9x1.6mm, Pitch 0.95mm, Lead Span 2.7mm, IPC High Density)
footprint SOT-23-OT5_M (SOT23, 5-Leads, Body 2.9x1.6mm, Pitch 0.95mm, Lead Span 2.7mm, IPC Low Density)
pins: 1 VIN (power), 2 VSS (power), 3 ~{SHDN} (in), 4 NC, 5 VOUT (power)

## MCP1801T-3302I/OT
designator U?
150 mA, High PSRR, Low Quiescent Current LDO, 5-Pin SOT-23, Industrial Temperature, Tape and Reel
footprint SOT-23-OT5_N (SOT23, 5-Leads, Body 2.9x1.6mm, Pitch 0.95mm, Lead Span 2.7mm, IPC Medium Density)
footprint SOT-23-OT5_L (SOT23, 5-Leads, Body 2.9x1.6mm, Pitch 0.95mm, Lead Span 2.7mm, IPC High Density)
footprint SOT-23-OT5_M (SOT23, 5-Leads, Body 2.9x1.6mm, Pitch 0.95mm, Lead Span 2.7mm, IPC Low Density)
pins: 1 VIN (power), 2 VSS (power), 3 ~{SHDN} (in), 4 NC, 5 VOUT (power)

## MCP1801T-5002I/OT
designator U?
150 mA, High PSRR, Low Quiescent Current LDO, 5-Pin SOT-23, Industrial Temperature, Tape and Reel
footprint SOT-23-OT5_N (SOT23, 5-Leads, Body 2.9x1.6mm, Pitch 0.95mm, Lead Span 2.7mm, IPC Medium Density)
footprint SOT-23-OT5_L (SOT23, 5-Leads, Body 2.9x1.6mm, Pitch 0.95mm, Lead Span 2.7mm, IPC High Density)
footprint SOT-23-OT5_M (SOT23, 5-Leads, Body 2.9x1.6mm, Pitch 0.95mm, Lead Span 2.7mm, IPC Low Density)
pins: 1 VIN (power), 2 VSS (power), 3 ~{SHDN} (in), 4 NC, 5 VOUT (power)

## MCP1801T-6002I/OT
designator U?
150 mA, High PSRR, Low Quiescent Current LDO, 5-Pin SOT-23, Industrial Temperature, Tape and Reel
footprint SOT-23-OT5_N (SOT23, 5-Leads, Body 2.9x1.6mm, Pitch 0.95mm, Lead Span 2.7mm, IPC Medium Density)
footprint SOT-23-OT5_L (SOT23, 5-Leads, Body 2.9x1.6mm, Pitch 0.95mm, Lead Span 2.7mm, IPC High Density)
footprint SOT-23-OT5_M (SOT23, 5-Leads, Body 2.9x1.6mm, Pitch 0.95mm, Lead Span 2.7mm, IPC Low Density)
pins: 1 VIN (power), 2 VSS (power), 3 ~{SHDN} (in), 4 NC, 5 VOUT (power)

## MCP1802T-0902I/OT
designator U?
300 mA, High PSRR, Low Quiescent Current LDO, 5-Pin SOT-23, Industrial Temperature, Tape and Reel
footprint SOT-23-OT5_N (SOT23, 5-Leads, Body 2.9x1.6mm, Pitch 0.95mm, Lead Span 2.7mm, IPC Medium Density)
footprint SOT-23-OT5_L (SOT23, 5-Leads, Body 2.9x1.6mm, Pitch 0.95mm, Lead Span 2.7mm, IPC High Density)
footprint SOT-23-OT5_M (SOT23, 5-Leads, Body 2.9x1.6mm, Pitch 0.95mm, Lead Span 2.7mm, IPC Low Density)
pins: 1 VIN (power), 2 VSS (power), 3 ~{SHDN} (in), 4 NC, 5 VOUT (power)

## MCP1802T-1202I/OT
designator U?
300 mA, High PSRR, Low Quiescent Current LDO, 5-Pin SOT-23, Industrial Temperature, Tape and Reel
footprint SOT-23-OT5_N (SOT23, 5-Leads, Body 2.9x1.6mm, Pitch 0.95mm, Lead Span 2.7mm, IPC Medium Density)
footprint SOT-23-OT5_L (SOT23, 5-Leads, Body 2.9x1.6mm, Pitch 0.95mm, Lead Span 2.7mm, IPC High Density)
footprint SOT-23-OT5_M (SOT23, 5-Leads, Body 2.9x1.6mm, Pitch 0.95mm, Lead Span 2.7mm, IPC Low Density)
pins: 1 VIN (power), 2 VSS (power), 3 ~{SHDN} (in), 4 NC, 5 VOUT (power)

## MCP1802T-1802I/OT
designator U?
300 mA, High PSRR, Low Quiescent Current LDO, 5-Pin SOT-23, Industrial Temperature, Tape and Reel
footprint SOT-23-OT5_N (SOT23, 5-Leads, Body 2.9x1.6mm, Pitch 0.95mm, Lead Span 2.7mm, IPC Medium Density)
footprint SOT-23-OT5_L (SOT23, 5-Leads, Body 2.9x1.6mm, Pitch 0.95mm, Lead Span 2.7mm, IPC High Density)
footprint SOT-23-OT5_M (SOT23, 5-Leads, Body 2.9x1.6mm, Pitch 0.95mm, Lead Span 2.7mm, IPC Low Density)
pins: 1 VIN (power), 2 VSS (power), 3 ~{SHDN} (in), 4 NC, 5 VOUT (power)

## MCP1802T-2502I/OT
designator U?
300 mA, High PSRR, Low Quiescent Current LDO, 5-Pin SOT-23, Industrial Temperature, Tape and Reel
footprint SOT-23-OT5_N (SOT23, 5-Leads, Body 2.9x1.6mm, Pitch 0.95mm, Lead Span 2.7mm, IPC Medium Density)
footprint SOT-23-OT5_L (SOT23, 5-Leads, Body 2.9x1.6mm, Pitch 0.95mm, Lead Span 2.7mm, IPC High Density)
footprint SOT-23-OT5_M (SOT23, 5-Leads, Body 2.9x1.6mm, Pitch 0.95mm, Lead Span 2.7mm, IPC Low Density)
pins: 1 VIN (power), 2 VSS (power), 3 ~{SHDN} (in), 4 NC, 5 VOUT (power)

## MCP1802T-3002I/OT
designator U?
300 mA, High PSRR, Low Quiescent Current LDO, 5-Pin SOT-23, Industrial Temperature, Tape and Reel
footprint SOT-23-OT5_N (SOT23, 5-Leads, Body 2.9x1.6mm, Pitch 0.95mm, Lead Span 2.7mm, IPC Medium Density)
footprint SOT-23-OT5_L (SOT23, 5-Leads, Body 2.9x1.6mm, Pitch 0.95mm, Lead Span 2.7mm, IPC High Density)
footprint SOT-23-OT5_M (SOT23, 5-Leads, Body 2.9x1.6mm, Pitch 0.95mm, Lead Span 2.7mm, IPC Low Density)
pins: 1 VIN (power), 2 VSS (power), 3 ~{SHDN} (in), 4 NC, 5 VOUT (power)

## MCP1802T-3302I/OT
designator U?
300 mA, High PSRR, Low Quiescent Current LDO, 5-Pin SOT-23, Industrial Temperature, Tape and Reel
footprint SOT-23-OT5_N (SOT23, 5-Leads, Body 2.9x1.6mm, Pitch 0.95mm, Lead Span 2.7mm, IPC Medium Density)
footprint SOT-23-OT5_L (SOT23, 5-Leads, Body 2.9x1.6mm, Pitch 0.95mm, Lead Span 2.7mm, IPC High Density)
footprint SOT-23-OT5_M (SOT23, 5-Leads, Body 2.9x1.6mm, Pitch 0.95mm, Lead Span 2.7mm, IPC Low Density)
pins: 1 VIN (power), 2 VSS (power), 3 ~{SHDN} (in), 4 NC, 5 VOUT (power)

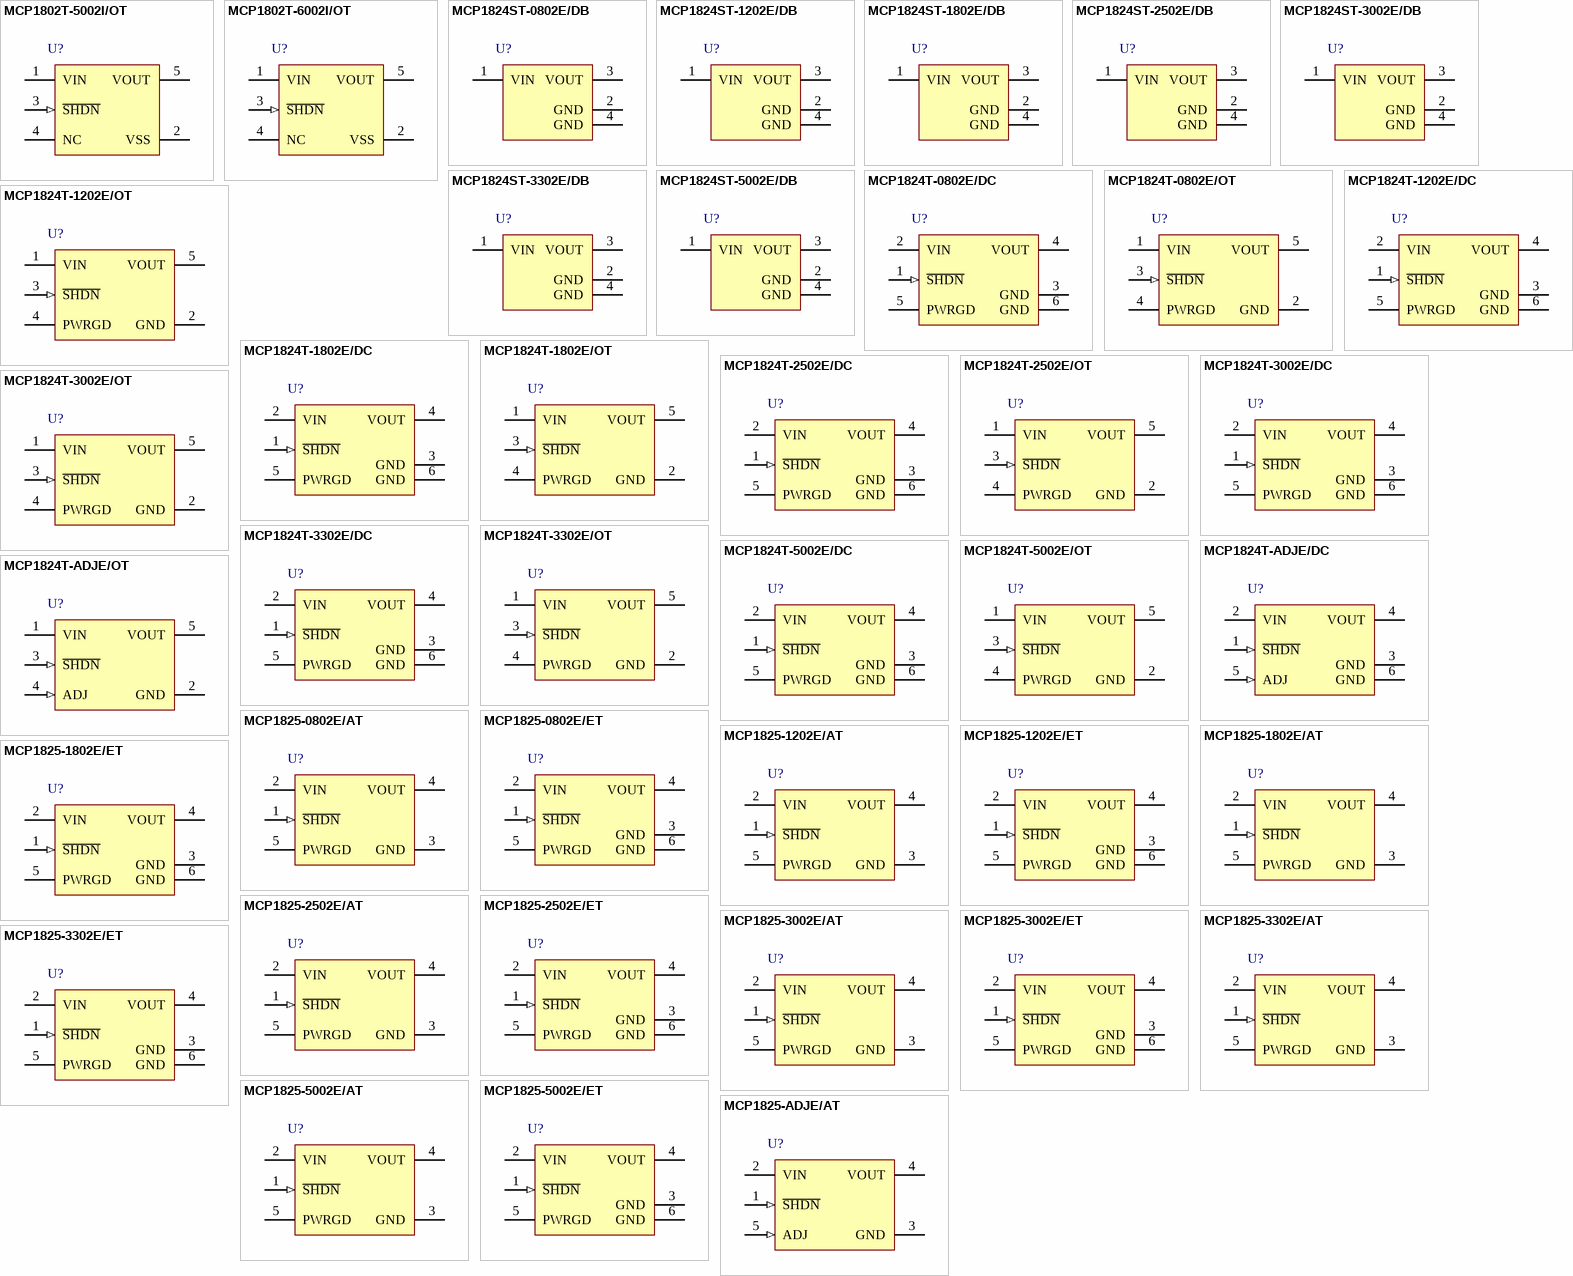
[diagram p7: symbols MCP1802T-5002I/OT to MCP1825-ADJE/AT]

## MCP1802T-5002I/OT
designator U?
300 mA, High PSRR, Low Quiescent Current LDO, 5-Pin SOT-23, Industrial Temperature, Tape and Reel
footprint SOT-23-OT5_N (SOT23, 5-Leads, Body 2.9x1.6mm, Pitch 0.95mm, Lead Span 2.7mm, IPC Medium Density)
footprint SOT-23-OT5_L (SOT23, 5-Leads, Body 2.9x1.6mm, Pitch 0.95mm, Lead Span 2.7mm, IPC High Density)
footprint SOT-23-OT5_M (SOT23, 5-Leads, Body 2.9x1.6mm, Pitch 0.95mm, Lead Span 2.7mm, IPC Low Density)
pins: 1 VIN (power), 2 VSS (power), 3 ~{SHDN} (in), 4 NC, 5 VOUT (power)

## MCP1802T-6002I/OT
designator U?
300 mA, High PSRR, Low Quiescent Current LDO, 5-Pin SOT-23, Industrial Temperature, Tape and Reel
footprint SOT-23-OT5_N (SOT23, 5-Leads, Body 2.9x1.6mm, Pitch 0.95mm, Lead Span 2.7mm, IPC Medium Density)
footprint SOT-23-OT5_L (SOT23, 5-Leads, Body 2.9x1.6mm, Pitch 0.95mm, Lead Span 2.7mm, IPC High Density)
footprint SOT-23-OT5_M (SOT23, 5-Leads, Body 2.9x1.6mm, Pitch 0.95mm, Lead Span 2.7mm, IPC Low Density)
pins: 1 VIN (power), 2 VSS (power), 3 ~{SHDN} (in), 4 NC, 5 VOUT (power)

## MCP1824ST-0802E/DB
designator U?
300 mA, Low Voltage, Low Quiescent Current LDO Regulator, 3-Pin SOT-223, Extended Temperature, Tape and Reel
footprint SOT-223-DB3_N (SOT223, 4-Leads, Body 6.5x3.5mm, Pitch 2.3mm, Lead Span 7mm, IPC Medium Density)
footprint SOT-223-DB3_L (SOT223, 4-Leads, Body 6.5x3.5mm, Pitch 2.3mm, Lead Span 7mm, IPC High Density)
footprint SOT-223-DB3_M (SOT223, 4-Leads, Body 6.5x3.5mm, Pitch 2.3mm, Lead Span 7mm, IPC Low Density)
pins: 1 VIN (power), 2 GND (power), 3 VOUT (power), 4 GND (power)

## MCP1824ST-1202E/DB
designator U?
300 mA, Low Voltage, Low Quiescent Current LDO Regulator, 3-Pin SOT-223, Extended Temperature, Tape and Reel
footprint SOT-223-DB3_N (SOT223, 4-Leads, Body 6.5x3.5mm, Pitch 2.3mm, Lead Span 7mm, IPC Medium Density)
footprint SOT-223-DB3_L (SOT223, 4-Leads, Body 6.5x3.5mm, Pitch 2.3mm, Lead Span 7mm, IPC High Density)
footprint SOT-223-DB3_M (SOT223, 4-Leads, Body 6.5x3.5mm, Pitch 2.3mm, Lead Span 7mm, IPC Low Density)
pins: 1 VIN (power), 2 GND (power), 3 VOUT (power), 4 GND (power)

## MCP1824ST-1802E/DB
designator U?
300 mA, Low Voltage, Low Quiescent Current LDO Regulator, 3-Pin SOT-223, Extended Temperature, Tape and Reel
footprint SOT-223-DB3_N (SOT223, 4-Leads, Body 6.5x3.5mm, Pitch 2.3mm, Lead Span 7mm, IPC Medium Density)
footprint SOT-223-DB3_L (SOT223, 4-Leads, Body 6.5x3.5mm, Pitch 2.3mm, Lead Span 7mm, IPC High Density)
footprint SOT-223-DB3_M (SOT223, 4-Leads, Body 6.5x3.5mm, Pitch 2.3mm, Lead Span 7mm, IPC Low Density)
pins: 1 VIN (power), 2 GND (power), 3 VOUT (power), 4 GND (power)

## MCP1824ST-2502E/DB
designator U?
300 mA, Low Voltage, Low Quiescent Current LDO Regulator, 3-Pin SOT-223, Extended Temperature, Tape and Reel
footprint SOT-223-DB3_N (SOT223, 4-Leads, Body 6.5x3.5mm, Pitch 2.3mm, Lead Span 7mm, IPC Medium Density)
footprint SOT-223-DB3_L (SOT223, 4-Leads, Body 6.5x3.5mm, Pitch 2.3mm, Lead Span 7mm, IPC High Density)
footprint SOT-223-DB3_M (SOT223, 4-Leads, Body 6.5x3.5mm, Pitch 2.3mm, Lead Span 7mm, IPC Low Density)
pins: 1 VIN (power), 2 GND (power), 3 VOUT (power), 4 GND (power)

## MCP1824ST-3002E/DB
designator U?
300 mA, Low Voltage, Low Quiescent Current LDO Regulator, 3-Pin SOT-223, Extended Temperature, Tape and Reel
footprint SOT-223-DB3_N (SOT223, 4-Leads, Body 6.5x3.5mm, Pitch 2.3mm, Lead Span 7mm, IPC Medium Density)
footprint SOT-223-DB3_L (SOT223, 4-Leads, Body 6.5x3.5mm, Pitch 2.3mm, Lead Span 7mm, IPC High Density)
footprint SOT-223-DB3_M (SOT223, 4-Leads, Body 6.5x3.5mm, Pitch 2.3mm, Lead Span 7mm, IPC Low Density)
pins: 1 VIN (power), 2 GND (power), 3 VOUT (power), 4 GND (power)

## MCP1824ST-3302E/DB
designator U?
300 mA, Low Voltage, Low Quiescent Current LDO Regulator, 3-Pin SOT-223, Extended Temperature, Tape and Reel
footprint SOT-223-DB3_N (SOT223, 4-Leads, Body 6.5x3.5mm, Pitch 2.3mm, Lead Span 7mm, IPC Medium Density)
footprint SOT-223-DB3_L (SOT223, 4-Leads, Body 6.5x3.5mm, Pitch 2.3mm, Lead Span 7mm, IPC High Density)
footprint SOT-223-DB3_M (SOT223, 4-Leads, Body 6.5x3.5mm, Pitch 2.3mm, Lead Span 7mm, IPC Low Density)
pins: 1 VIN (power), 2 GND (power), 3 VOUT (power), 4 GND (power)

## MCP1824ST-5002E/DB
designator U?
300 mA, Low Voltage, Low Quiescent Current LDO Regulator, 3-Pin SOT-223, Extended Temperature, Tape and Reel
footprint SOT-223-DB3_N (SOT223, 4-Leads, Body 6.5x3.5mm, Pitch 2.3mm, Lead Span 7mm, IPC Medium Density)
footprint SOT-223-DB3_L (SOT223, 4-Leads, Body 6.5x3.5mm, Pitch 2.3mm, Lead Span 7mm, IPC High Density)
footprint SOT-223-DB3_M (SOT223, 4-Leads, Body 6.5x3.5mm, Pitch 2.3mm, Lead Span 7mm, IPC Low Density)
pins: 1 VIN (power), 2 GND (power), 3 VOUT (power), 4 GND (power)

## MCP1824T-0802E/DC
designator U?
300 mA, Low Voltage, Low Quiescent Current LDO Regulator, 5-Pin SOT-223, Extended Temperature, Tape and Reel
footprint SOT-223-DC5_N (SOT223, 6-Leads, Body 6.5x3.5mm, Pitch 1.27mm, Lead Span 7mm, IPC Medium Density)
footprint SOT-223-DC5_L (SOT223, 6-Leads, Body 6.5x3.5mm, Pitch 1.27mm, Lead Span 7mm, IPC High Density)
footprint SOT-223-DC5_M (SOT223, 6-Leads, Body 6.5x3.5mm, Pitch 1.27mm, Lead Span 7mm, IPC Low Density)
pins: 1 ~{SHDN} (in), 2 VIN (power), 3 GND (power), 4 VOUT (power), 5 PWRGD (power), 6 GND (power)

## MCP1824T-0802E/OT
designator U?
300 mA, Low Voltage, Low Quiescent Current LDO Regulator, 5-Pin SOT-23, Extended Temperature, Tape and Reel
footprint SOT-23-OT5_N (SOT23, 5-Leads, Body 2.9x1.6mm, Pitch 0.95mm, Lead Span 2.7mm, IPC Medium Density)
footprint SOT-23-OT5_L (SOT23, 5-Leads, Body 2.9x1.6mm, Pitch 0.95mm, Lead Span 2.7mm, IPC High Density)
footprint SOT-23-OT5_M (SOT23, 5-Leads, Body 2.9x1.6mm, Pitch 0.95mm, Lead Span 2.7mm, IPC Low Density)
pins: 1 VIN (power), 2 GND (power), 3 ~{SHDN} (in), 4 PWRGD (power), 5 VOUT (power)

## MCP1824T-1202E/DC
designator U?
300 mA, Low Voltage, Low Quiescent Current LDO Regulator, 5-Pin SOT-223, Extended Temperature, Tape and Reel
footprint SOT-223-DC5_N (SOT223, 6-Leads, Body 6.5x3.5mm, Pitch 1.27mm, Lead Span 7mm, IPC Medium Density)
footprint SOT-223-DC5_L (SOT223, 6-Leads, Body 6.5x3.5mm, Pitch 1.27mm, Lead Span 7mm, IPC High Density)
footprint SOT-223-DC5_M (SOT223, 6-Leads, Body 6.5x3.5mm, Pitch 1.27mm, Lead Span 7mm, IPC Low Density)
pins: 1 ~{SHDN} (in), 2 VIN (power), 3 GND (power), 4 VOUT (power), 5 PWRGD (power), 6 GND (power)

## MCP1824T-1202E/OT
designator U?
300 mA, Low Voltage, Low Quiescent Current LDO Regulator, 5-Pin SOT-23, Extended Temperature, Tape and Reel
footprint SOT-23-OT5_N (SOT23, 5-Leads, Body 2.9x1.6mm, Pitch 0.95mm, Lead Span 2.7mm, IPC Medium Density)
footprint SOT-23-OT5_L (SOT23, 5-Leads, Body 2.9x1.6mm, Pitch 0.95mm, Lead Span 2.7mm, IPC High Density)
footprint SOT-23-OT5_M (SOT23, 5-Leads, Body 2.9x1.6mm, Pitch 0.95mm, Lead Span 2.7mm, IPC Low Density)
pins: 1 VIN (power), 2 GND (power), 3 ~{SHDN} (in), 4 PWRGD (power), 5 VOUT (power)

## MCP1824T-1802E/DC
designator U?
300 mA, Low Voltage, Low Quiescent Current LDO Regulator, 5-Pin SOT-223, Extended Temperature, Tape and Reel
footprint SOT-223-DC5_N (SOT223, 6-Leads, Body 6.5x3.5mm, Pitch 1.27mm, Lead Span 7mm, IPC Medium Density)
footprint SOT-223-DC5_L (SOT223, 6-Leads, Body 6.5x3.5mm, Pitch 1.27mm, Lead Span 7mm, IPC High Density)
footprint SOT-223-DC5_M (SOT223, 6-Leads, Body 6.5x3.5mm, Pitch 1.27mm, Lead Span 7mm, IPC Low Density)
pins: 1 ~{SHDN} (in), 2 VIN (power), 3 GND (power), 4 VOUT (power), 5 PWRGD (power), 6 GND (power)

## MCP1824T-1802E/OT
designator U?
300 mA, Low Voltage, Low Quiescent Current LDO Regulator, 5-Pin SOT-23, Extended Temperature, Tape and Reel
footprint SOT-23-OT5_N (SOT23, 5-Leads, Body 2.9x1.6mm, Pitch 0.95mm, Lead Span 2.7mm, IPC Medium Density)
footprint SOT-23-OT5_L (SOT23, 5-Leads, Body 2.9x1.6mm, Pitch 0.95mm, Lead Span 2.7mm, IPC High Density)
footprint SOT-23-OT5_M (SOT23, 5-Leads, Body 2.9x1.6mm, Pitch 0.95mm, Lead Span 2.7mm, IPC Low Density)
pins: 1 VIN (power), 2 GND (power), 3 ~{SHDN} (in), 4 PWRGD (power), 5 VOUT (power)

## MCP1824T-2502E/DC
designator U?
300 mA, Low Voltage, Low Quiescent Current LDO Regulator, 5-Pin SOT-223, Extended Temperature, Tape and Reel
footprint SOT-223-DC5_N (SOT223, 6-Leads, Body 6.5x3.5mm, Pitch 1.27mm, Lead Span 7mm, IPC Medium Density)
footprint SOT-223-DC5_L (SOT223, 6-Leads, Body 6.5x3.5mm, Pitch 1.27mm, Lead Span 7mm, IPC High Density)
footprint SOT-223-DC5_M (SOT223, 6-Leads, Body 6.5x3.5mm, Pitch 1.27mm, Lead Span 7mm, IPC Low Density)
pins: 1 ~{SHDN} (in), 2 VIN (power), 3 GND (power), 4 VOUT (power), 5 PWRGD (power), 6 GND (power)

## MCP1824T-2502E/OT
designator U?
300 mA, Low Voltage, Low Quiescent Current LDO Regulator, 5-Pin SOT-23, Extended Temperature, Tape and Reel
footprint SOT-23-OT5_N (SOT23, 5-Leads, Body 2.9x1.6mm, Pitch 0.95mm, Lead Span 2.7mm, IPC Medium Density)
footprint SOT-23-OT5_L (SOT23, 5-Leads, Body 2.9x1.6mm, Pitch 0.95mm, Lead Span 2.7mm, IPC High Density)
footprint SOT-23-OT5_M (SOT23, 5-Leads, Body 2.9x1.6mm, Pitch 0.95mm, Lead Span 2.7mm, IPC Low Density)
pins: 1 VIN (power), 2 GND (power), 3 ~{SHDN} (in), 4 PWRGD (power), 5 VOUT (power)

## MCP1824T-3002E/DC
designator U?
300 mA, Low Voltage, Low Quiescent Current LDO Regulator, 5-Pin SOT-223, Extended Temperature, Tape and Reel
footprint SOT-223-DC5_N (SOT223, 6-Leads, Body 6.5x3.5mm, Pitch 1.27mm, Lead Span 7mm, IPC Medium Density)
footprint SOT-223-DC5_L (SOT223, 6-Leads, Body 6.5x3.5mm, Pitch 1.27mm, Lead Span 7mm, IPC High Density)
footprint SOT-223-DC5_M (SOT223, 6-Leads, Body 6.5x3.5mm, Pitch 1.27mm, Lead Span 7mm, IPC Low Density)
pins: 1 ~{SHDN} (in), 2 VIN (power), 3 GND (power), 4 VOUT (power), 5 PWRGD (power), 6 GND (power)

## MCP1824T-3002E/OT
designator U?
300 mA, Low Voltage, Low Quiescent Current LDO Regulator, 5-Pin SOT-23, Extended Temperature, Tape and Reel
footprint SOT-23-OT5_N (SOT23, 5-Leads, Body 2.9x1.6mm, Pitch 0.95mm, Lead Span 2.7mm, IPC Medium Density)
footprint SOT-23-OT5_L (SOT23, 5-Leads, Body 2.9x1.6mm, Pitch 0.95mm, Lead Span 2.7mm, IPC High Density)
footprint SOT-23-OT5_M (SOT23, 5-Leads, Body 2.9x1.6mm, Pitch 0.95mm, Lead Span 2.7mm, IPC Low Density)
pins: 1 VIN (power), 2 GND (power), 3 ~{SHDN} (in), 4 PWRGD (power), 5 VOUT (power)

## MCP1824T-3302E/DC
designator U?
300 mA, Low Voltage, Low Quiescent Current LDO Regulator, 5-Pin SOT-223, Extended Temperature, Tape and Reel
footprint SOT-223-DC5_N (SOT223, 6-Leads, Body 6.5x3.5mm, Pitch 1.27mm, Lead Span 7mm, IPC Medium Density)
footprint SOT-223-DC5_L (SOT223, 6-Leads, Body 6.5x3.5mm, Pitch 1.27mm, Lead Span 7mm, IPC High Density)
footprint SOT-223-DC5_M (SOT223, 6-Leads, Body 6.5x3.5mm, Pitch 1.27mm, Lead Span 7mm, IPC Low Density)
pins: 1 ~{SHDN} (in), 2 VIN (power), 3 GND (power), 4 VOUT (power), 5 PWRGD (power), 6 GND (power)

## MCP1824T-3302E/OT
designator U?
300 mA, Low Voltage, Low Quiescent Current LDO Regulator, 5-Pin SOT-23, Extended Temperature, Tape and Reel
footprint SOT-23-OT5_N (SOT23, 5-Leads, Body 2.9x1.6mm, Pitch 0.95mm, Lead Span 2.7mm, IPC Medium Density)
footprint SOT-23-OT5_L (SOT23, 5-Leads, Body 2.9x1.6mm, Pitch 0.95mm, Lead Span 2.7mm, IPC High Density)
footprint SOT-23-OT5_M (SOT23, 5-Leads, Body 2.9x1.6mm, Pitch 0.95mm, Lead Span 2.7mm, IPC Low Density)
pins: 1 VIN (power), 2 GND (power), 3 ~{SHDN} (in), 4 PWRGD (power), 5 VOUT (power)

## MCP1824T-5002E/DC
designator U?
300 mA, Low Voltage, Low Quiescent Current LDO Regulator, 5-Pin SOT-223, Extended Temperature, Tape and Reel
footprint SOT-223-DC5_N (SOT223, 6-Leads, Body 6.5x3.5mm, Pitch 1.27mm, Lead Span 7mm, IPC Medium Density)
footprint SOT-223-DC5_L (SOT223, 6-Leads, Body 6.5x3.5mm, Pitch 1.27mm, Lead Span 7mm, IPC High Density)
footprint SOT-223-DC5_M (SOT223, 6-Leads, Body 6.5x3.5mm, Pitch 1.27mm, Lead Span 7mm, IPC Low Density)
pins: 1 ~{SHDN} (in), 2 VIN (power), 3 GND (power), 4 VOUT (power), 5 PWRGD (power), 6 GND (power)

## MCP1824T-5002E/OT
designator U?
300 mA, Low Voltage, Low Quiescent Current LDO Regulator, 5-Pin SOT-23, Extended Temperature, Tape and Reel
footprint SOT-23-OT5_N (SOT23, 5-Leads, Body 2.9x1.6mm, Pitch 0.95mm, Lead Span 2.7mm, IPC Medium Density)
footprint SOT-23-OT5_L (SOT23, 5-Leads, Body 2.9x1.6mm, Pitch 0.95mm, Lead Span 2.7mm, IPC High Density)
footprint SOT-23-OT5_M (SOT23, 5-Leads, Body 2.9x1.6mm, Pitch 0.95mm, Lead Span 2.7mm, IPC Low Density)
pins: 1 VIN (power), 2 GND (power), 3 ~{SHDN} (in), 4 PWRGD (power), 5 VOUT (power)

## MCP1824T-ADJE/DC
designator U?
300 mA, Low Voltage, Low Quiescent Current LDO Regulator, 5-Pin SOT-223, Extended Temperature, Tape and Reel
footprint SOT-223-DC5_N (SOT223, 6-Leads, Body 6.5x3.5mm, Pitch 1.27mm, Lead Span 7mm, IPC Medium Density)
footprint SOT-223-DC5_L (SOT223, 6-Leads, Body 6.5x3.5mm, Pitch 1.27mm, Lead Span 7mm, IPC High Density)
footprint SOT-223-DC5_M (SOT223, 6-Leads, Body 6.5x3.5mm, Pitch 1.27mm, Lead Span 7mm, IPC Low Density)
pins: 1 ~{SHDN} (in), 2 VIN (power), 3 GND (power), 4 VOUT (power), 5 ADJ (in), 6 GND (power)

## MCP1824T-ADJE/OT
designator U?
300 mA, Low Voltage, Low Quiescent Current LDO Regulator, 5-Pin SOT-23, Extended Temperature, Tape and Reel
footprint SOT-23-OT5_N (SOT23, 5-Leads, Body 2.9x1.6mm, Pitch 0.95mm, Lead Span 2.7mm, IPC Medium Density)
footprint SOT-23-OT5_L (SOT23, 5-Leads, Body 2.9x1.6mm, Pitch 0.95mm, Lead Span 2.7mm, IPC High Density)
footprint SOT-23-OT5_M (SOT23, 5-Leads, Body 2.9x1.6mm, Pitch 0.95mm, Lead Span 2.7mm, IPC Low Density)
pins: 1 VIN (power), 2 GND (power), 3 ~{SHDN} (in), 4 ADJ (in), 5 VOUT (power)

## MCP1825-0802E/AT
designator U?
500 mA, Low Voltage, Low Quiescent Current LDO Regulator, 5-Pin TO-220, Extended Temperature
footprint TO-220-AT5 (TO, Thru-Hole, Vertical, Heatsink Mounted; 5 In-Line Leads; Pitch 1.70 mm)
pins: 1 ~{SHDN} (in), 2 VIN (power), 3 GND (power), 4 VOUT (power), 5 PWRGD (power)

## MCP1825-0802E/ET
designator U?
500 mA, Low Voltage, Low Quiescent Current LDO Regulator, 5-Pin DDPAK, Extended Temperature
footprint DDPAK-ET5_N (D2-PAK, 6-Leads, Body 9x10.2mm, Pitch 1.7mm, Lead Span 14.9mm, IPC Medium Density)
footprint DDPAK-ET5_L (D2-PAK, 6-Leads, Body 9x10.2mm, Pitch 1.7mm, Lead Span 14.9mm, IPC High Density)
footprint DDPAK-ET5_M (D2-PAK, 6-Leads, Body 9x10.2mm, Pitch 1.7mm, Lead Span 14.9mm, IPC Low Density)
pins: 1 ~{SHDN} (in), 2 VIN (power), 3 GND (power), 4 VOUT (power), 5 PWRGD (power), 6 GND (power)

## MCP1825-1202E/AT
designator U?
500 mA, Low Voltage, Low Quiescent Current LDO Regulator, 5-Pin TO-220, Extended Temperature
footprint TO-220-AT5 (TO, Thru-Hole, Vertical, Heatsink Mounted; 5 In-Line Leads; Pitch 1.70 mm)
pins: 1 ~{SHDN} (in), 2 VIN (power), 3 GND (power), 4 VOUT (power), 5 PWRGD (power)

## MCP1825-1202E/ET
designator U?
500 mA, Low Voltage, Low Quiescent Current LDO Regulator, 5-Pin DDPAK, Extended Temperature
footprint DDPAK-ET5_N (D2-PAK, 6-Leads, Body 9x10.2mm, Pitch 1.7mm, Lead Span 14.9mm, IPC Medium Density)
footprint DDPAK-ET5_L (D2-PAK, 6-Leads, Body 9x10.2mm, Pitch 1.7mm, Lead Span 14.9mm, IPC High Density)
footprint DDPAK-ET5_M (D2-PAK, 6-Leads, Body 9x10.2mm, Pitch 1.7mm, Lead Span 14.9mm, IPC Low Density)
pins: 1 ~{SHDN} (in), 2 VIN (power), 3 GND (power), 4 VOUT (power), 5 PWRGD (power), 6 GND (power)

## MCP1825-1802E/AT
designator U?
500 mA, Low Voltage, Low Quiescent Current LDO Regulator, 5-Pin TO-220, Extended Temperature
footprint TO-220-AT5 (TO, Thru-Hole, Vertical, Heatsink Mounted; 5 In-Line Leads; Pitch 1.70 mm)
pins: 1 ~{SHDN} (in), 2 VIN (power), 3 GND (power), 4 VOUT (power), 5 PWRGD (power)

## MCP1825-1802E/ET
designator U?
500 mA, Low Voltage, Low Quiescent Current LDO Regulator, 5-Pin DDPAK, Extended Temperature
footprint DDPAK-ET5_N (D2-PAK, 6-Leads, Body 9x10.2mm, Pitch 1.7mm, Lead Span 14.9mm, IPC Medium Density)
footprint DDPAK-ET5_L (D2-PAK, 6-Leads, Body 9x10.2mm, Pitch 1.7mm, Lead Span 14.9mm, IPC High Density)
footprint DDPAK-ET5_M (D2-PAK, 6-Leads, Body 9x10.2mm, Pitch 1.7mm, Lead Span 14.9mm, IPC Low Density)
pins: 1 ~{SHDN} (in), 2 VIN (power), 3 GND (power), 4 VOUT (power), 5 PWRGD (power), 6 GND (power)

## MCP1825-2502E/AT
designator U?
500 mA, Low Voltage, Low Quiescent Current LDO Regulator, 5-Pin TO-220, Extended Temperature
footprint TO-220-AT5 (TO, Thru-Hole, Vertical, Heatsink Mounted; 5 In-Line Leads; Pitch 1.70 mm)
pins: 1 ~{SHDN} (in), 2 VIN (power), 3 GND (power), 4 VOUT (power), 5 PWRGD (power)

## MCP1825-2502E/ET
designator U?
500 mA, Low Voltage, Low Quiescent Current LDO Regulator, 5-Pin DDPAK, Extended Temperature
footprint DDPAK-ET5_N (D2-PAK, 6-Leads, Body 9x10.2mm, Pitch 1.7mm, Lead Span 14.9mm, IPC Medium Density)
footprint DDPAK-ET5_L (D2-PAK, 6-Leads, Body 9x10.2mm, Pitch 1.7mm, Lead Span 14.9mm, IPC High Density)
footprint DDPAK-ET5_M (D2-PAK, 6-Leads, Body 9x10.2mm, Pitch 1.7mm, Lead Span 14.9mm, IPC Low Density)
pins: 1 ~{SHDN} (in), 2 VIN (power), 3 GND (power), 4 VOUT (power), 5 PWRGD (power), 6 GND (power)

## MCP1825-3002E/AT
designator U?
500 mA, Low Voltage, Low Quiescent Current LDO Regulator, 5-Pin TO-220, Extended Temperature
footprint TO-220-AT5 (TO, Thru-Hole, Vertical, Heatsink Mounted; 5 In-Line Leads; Pitch 1.70 mm)
pins: 1 ~{SHDN} (in), 2 VIN (power), 3 GND (power), 4 VOUT (power), 5 PWRGD (power)

## MCP1825-3002E/ET
designator U?
500 mA, Low Voltage, Low Quiescent Current LDO Regulator, 5-Pin DDPAK, Extended Temperature
footprint DDPAK-ET5_N (D2-PAK, 6-Leads, Body 9x10.2mm, Pitch 1.7mm, Lead Span 14.9mm, IPC Medium Density)
footprint DDPAK-ET5_L (D2-PAK, 6-Leads, Body 9x10.2mm, Pitch 1.7mm, Lead Span 14.9mm, IPC High Density)
footprint DDPAK-ET5_M (D2-PAK, 6-Leads, Body 9x10.2mm, Pitch 1.7mm, Lead Span 14.9mm, IPC Low Density)
pins: 1 ~{SHDN} (in), 2 VIN (power), 3 GND (power), 4 VOUT (power), 5 PWRGD (power), 6 GND (power)

## MCP1825-3302E/AT
designator U?
500 mA, Low Voltage, Low Quiescent Current LDO Regulator, 5-Pin TO-220, Extended Temperature
footprint TO-220-AT5 (TO, Thru-Hole, Vertical, Heatsink Mounted; 5 In-Line Leads; Pitch 1.70 mm)
pins: 1 ~{SHDN} (in), 2 VIN (power), 3 GND (power), 4 VOUT (power), 5 PWRGD (power)

## MCP1825-3302E/ET
designator U?
500 mA, Low Voltage, Low Quiescent Current LDO Regulator, 5-Pin DDPAK, Extended Temperature
footprint DDPAK-ET5_N (D2-PAK, 6-Leads, Body 9x10.2mm, Pitch 1.7mm, Lead Span 14.9mm, IPC Medium Density)
footprint DDPAK-ET5_L (D2-PAK, 6-Leads, Body 9x10.2mm, Pitch 1.7mm, Lead Span 14.9mm, IPC High Density)
footprint DDPAK-ET5_M (D2-PAK, 6-Leads, Body 9x10.2mm, Pitch 1.7mm, Lead Span 14.9mm, IPC Low Density)
pins: 1 ~{SHDN} (in), 2 VIN (power), 3 GND (power), 4 VOUT (power), 5 PWRGD (power), 6 GND (power)

## MCP1825-5002E/AT
designator U?
500 mA, Low Voltage, Low Quiescent Current LDO Regulator, 5-Pin TO-220, Extended Temperature
footprint TO-220-AT5 (TO, Thru-Hole, Vertical, Heatsink Mounted; 5 In-Line Leads; Pitch 1.70 mm)
pins: 1 ~{SHDN} (in), 2 VIN (power), 3 GND (power), 4 VOUT (power), 5 PWRGD (power)

## MCP1825-5002E/ET
designator U?
500 mA, Low Voltage, Low Quiescent Current LDO Regulator, 5-Pin DDPAK, Extended Temperature
footprint DDPAK-ET5_N (D2-PAK, 6-Leads, Body 9x10.2mm, Pitch 1.7mm, Lead Span 14.9mm, IPC Medium Density)
footprint DDPAK-ET5_L (D2-PAK, 6-Leads, Body 9x10.2mm, Pitch 1.7mm, Lead Span 14.9mm, IPC High Density)
footprint DDPAK-ET5_M (D2-PAK, 6-Leads, Body 9x10.2mm, Pitch 1.7mm, Lead Span 14.9mm, IPC Low Density)
pins: 1 ~{SHDN} (in), 2 VIN (power), 3 GND (power), 4 VOUT (power), 5 PWRGD (power), 6 GND (power)

## MCP1825-ADJE/AT
designator U?
500 mA, Low Voltage, Low Quiescent Current LDO Regulator, 5-Pin TO-220, Extended Temperature
footprint TO-220-AT5 (TO, Thru-Hole, Vertical, Heatsink Mounted; 5 In-Line Leads; Pitch 1.70 mm)
pins: 1 ~{SHDN} (in), 2 VIN (power), 3 GND (power), 4 VOUT (power), 5 ADJ (in)

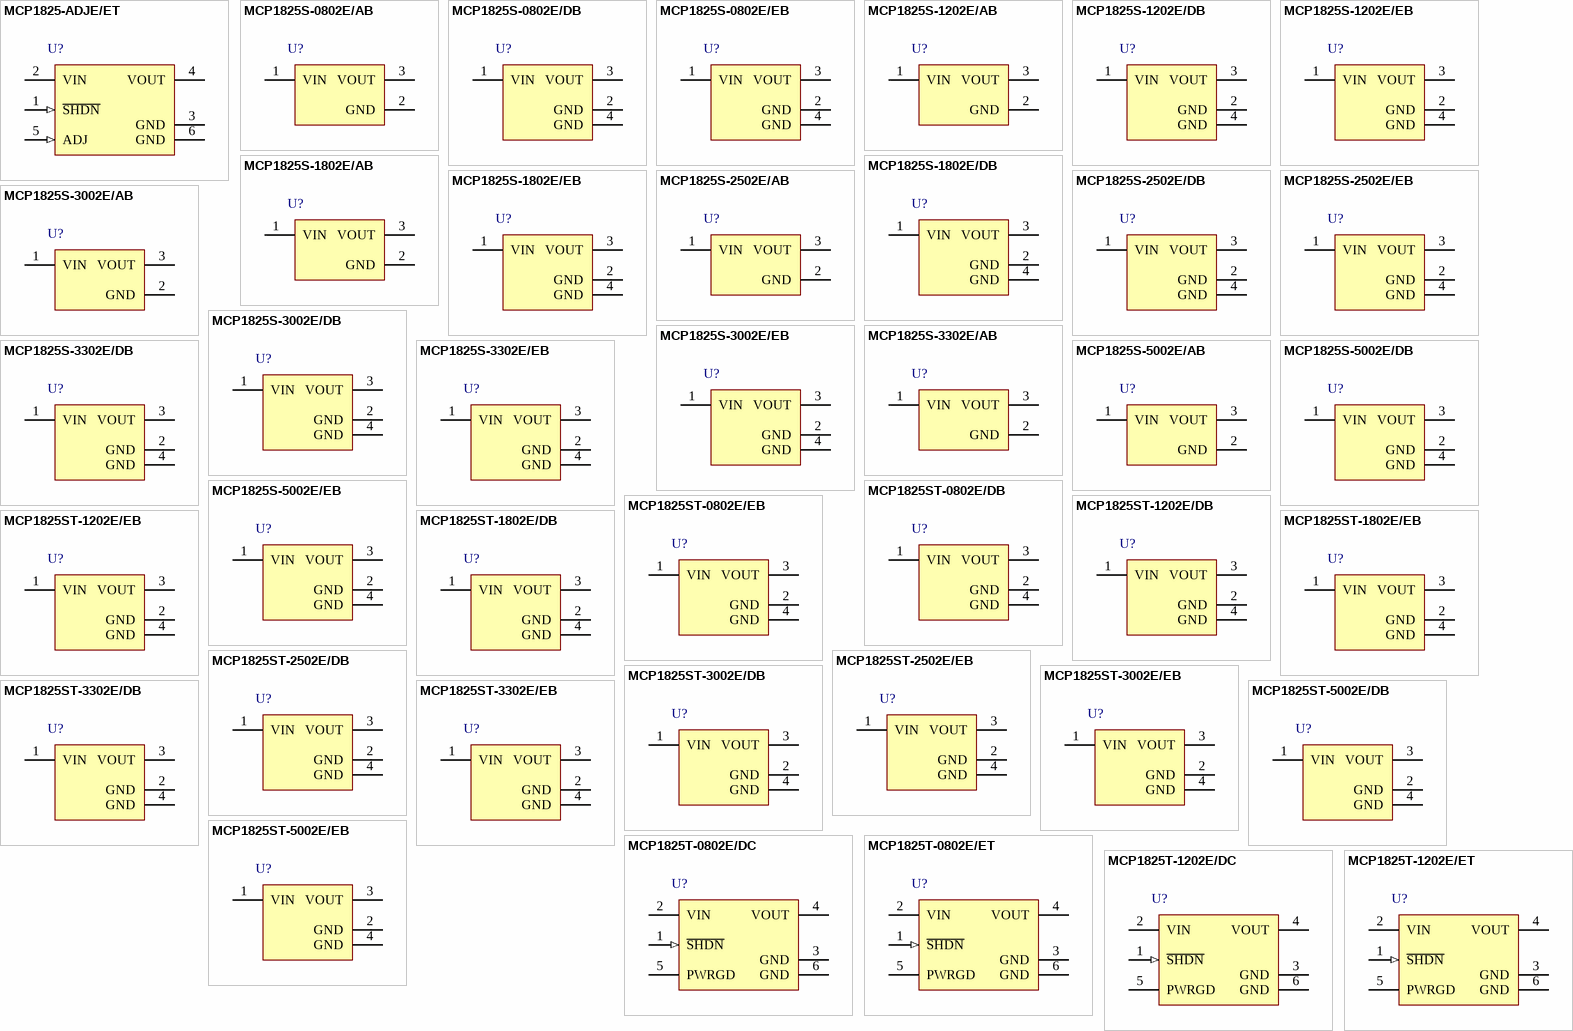
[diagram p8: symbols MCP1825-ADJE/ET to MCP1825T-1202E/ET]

## MCP1825-ADJE/ET
designator U?
500 mA, Low Voltage, Low Quiescent Current LDO Regulator, 5-Pin DDPAK, Extended Temperature
footprint DDPAK-ET5_N (D2-PAK, 6-Leads, Body 9x10.2mm, Pitch 1.7mm, Lead Span 14.9mm, IPC Medium Density)
footprint DDPAK-ET5_L (D2-PAK, 6-Leads, Body 9x10.2mm, Pitch 1.7mm, Lead Span 14.9mm, IPC High Density)
footprint DDPAK-ET5_M (D2-PAK, 6-Leads, Body 9x10.2mm, Pitch 1.7mm, Lead Span 14.9mm, IPC Low Density)
pins: 1 ~{SHDN} (in), 2 VIN (power), 3 GND (power), 4 VOUT (power), 5 ADJ (in), 6 GND (power)

## MCP1825S-0802E/AB
designator U?
500 mA, Low Voltage, Low Quiescent Current LDO Regulator, 3-Pin TO-220, Extended Temperature
footprint TO-220-AB3 (TO, Thru-Hole, Vertical, Heatsink Mounted; 3 In-Line Leads; Pitch 2.54 mm)
pins: 1 VIN (power), 2 GND (power), 3 VOUT (power)

## MCP1825S-0802E/DB
designator U?
500 mA, Low Voltage, Low Quiescent Current LDO Regulator, 3-Pin SOT-223, Extended Temperature
footprint SOT-223-DB3_N (SOT223, 4-Leads, Body 6.5x3.5mm, Pitch 2.3mm, Lead Span 7mm, IPC Medium Density)
footprint SOT-223-DB3_L (SOT223, 4-Leads, Body 6.5x3.5mm, Pitch 2.3mm, Lead Span 7mm, IPC High Density)
footprint SOT-223-DB3_M (SOT223, 4-Leads, Body 6.5x3.5mm, Pitch 2.3mm, Lead Span 7mm, IPC Low Density)
pins: 1 VIN (power), 2 GND (power), 3 VOUT (power), 4 GND (power)

## MCP1825S-0802E/EB
designator U?
500 mA, Low Voltage, Low Quiescent Current LDO Regulator, 3-Pin DDPAK, Extended Temperature
footprint DDPAK-EB3_N (D2-PAK, 4-Leads, Body 9x10.2mm, Pitch 2.54mm, Lead Span 14.9mm, IPC Medium Density)
footprint DDPAK-EB3_L (D2-PAK, 4-Leads, Body 9x10.2mm, Pitch 2.54mm, Lead Span 14.9mm, IPC High Density)
footprint DDPAK-EB3_M (D2-PAK, 4-Leads, Body 9x10.2mm, Pitch 2.54mm, Lead Span 14.9mm, IPC Low Density)
pins: 1 VIN (power), 2 GND (power), 3 VOUT (power), 4 GND (power)

## MCP1825S-1202E/AB
designator U?
500 mA, Low Voltage, Low Quiescent Current LDO Regulator, 3-Pin TO-220, Extended Temperature
footprint TO-220-AB3 (TO, Thru-Hole, Vertical, Heatsink Mounted; 3 In-Line Leads; Pitch 2.54 mm)
pins: 1 VIN (power), 2 GND (power), 3 VOUT (power)

## MCP1825S-1202E/DB
designator U?
500 mA, Low Voltage, Low Quiescent Current LDO Regulator, 3-Pin SOT-223, Extended Temperature
footprint SOT-223-DB3_N (SOT223, 4-Leads, Body 6.5x3.5mm, Pitch 2.3mm, Lead Span 7mm, IPC Medium Density)
footprint SOT-223-DB3_L (SOT223, 4-Leads, Body 6.5x3.5mm, Pitch 2.3mm, Lead Span 7mm, IPC High Density)
footprint SOT-223-DB3_M (SOT223, 4-Leads, Body 6.5x3.5mm, Pitch 2.3mm, Lead Span 7mm, IPC Low Density)
pins: 1 VIN (power), 2 GND (power), 3 VOUT (power), 4 GND (power)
